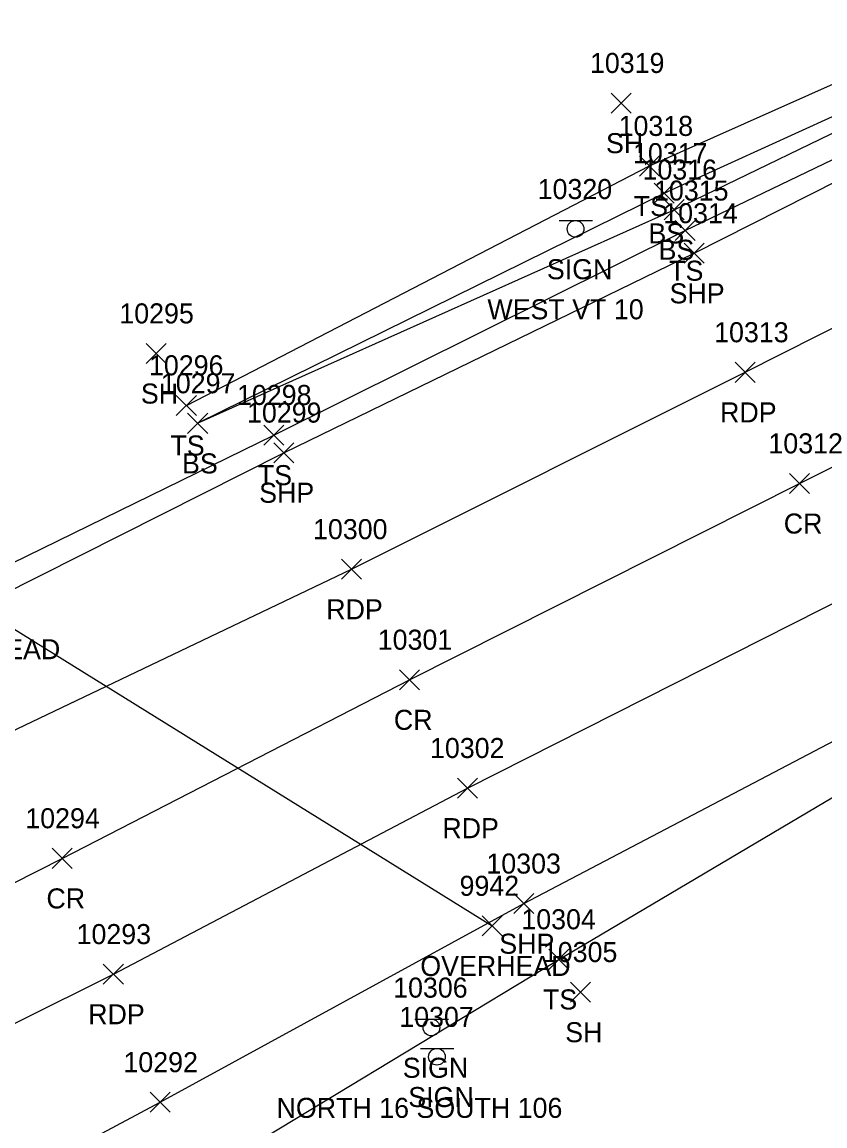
# Model space of a CAD drawing. Extents: x 1611797 to 1633212, y 298978 to 305475.
# Drawn here: x 1631797.1 to 1631877.3, y 304995.4 to 305105.6 of the extents above; entities that cross this region are included whole.
import ezdxf

# ---------------------------------------------------------------- set-up
doc = ezdxf.new("R2010")
doc.units = 0
for name, color, linetype in [('L_A', 7, 'Continuous'), ('L_I', 7, 'Continuous'), ('L_TIC', 7, 'Continuous'), ('LELB', 7, 'Continuous'), ('P_A', 7, 'Continuous'), ('P_I', 7, 'Continuous'), ('P_TIC', 7, 'Continuous'), ('PET', 7, 'Continuous'), ('PRC', 7, 'Continuous'), ('PSP', 7, 'Continuous'), ('S_A', 7, 'Continuous'), ('S_C', 7, 'Continuous'), ('S_I', 7, 'Continuous'), ('SSGN', 7, 'Continuous'), ('U_A', 7, 'Continuous'), ('U_I', 7, 'Continuous'), ('U_TIC', 7, 'Continuous'), ('UCO', 7, 'Continuous')]:
    doc.layers.add(name, color=color, linetype=linetype)

msp = doc.modelspace()

# ---------------------------------------------------------------- linework, layer by layer
at = {"layer": 'L_TIC'}
for points in [[(1631855.91, 305096.52), (1631857.91, 305098.52)], [(1631857.91, 305096.52), (1631855.91, 305098.52)], [(1631858.76, 305090.24), (1631860.76, 305092.24)], [(1631860.76, 305090.24), (1631858.76, 305092.24)], [(1631860.2, 305087.52), (1631862.2, 305089.52)], [(1631862.2, 305087.52), (1631860.2, 305089.52)], [(1631861.21, 305085.88), (1631863.21, 305087.88)], [(1631863.21, 305085.88), (1631861.21, 305087.88)], [(1631862.3, 305083.79), (1631864.3, 305085.79)], [(1631864.3, 305083.79), (1631862.3, 305085.79)], [(1631809.48, 305071.53), (1631811.48, 305073.53)], [(1631811.48, 305071.53), (1631809.48, 305073.53)], [(1631812.5, 305066.35), (1631814.5, 305068.35)], [(1631814.5, 305066.35), (1631812.5, 305068.35)], [(1631813.63, 305064.56), (1631815.63, 305066.56)], [(1631815.63, 305064.56), (1631813.63, 305066.56)], [(1631813.63, 305064.56), (1631815.63, 305066.56)], [(1631815.63, 305064.56), (1631813.63, 305066.56)], [(1631821.23, 305063.39), (1631823.23, 305065.39)], [(1631823.23, 305063.39), (1631821.23, 305065.39)], [(1631849.7, 305011.07), (1631851.7, 305013.07)], [(1631851.7, 305011.07), (1631849.7, 305013.07)], [(1631851.85, 305007.8), (1631853.85, 305009.8)], [(1631853.85, 305007.8), (1631851.85, 305009.8)]]:
    msp.add_lwpolyline(points, dxfattribs=at)
at = {"layer": 'LELB'}
for points in [[(1631813.5, 305067.35), (1631859.76, 305091.24), (1631897.69, 305108.2), (1631899.73, 305104.65), (1631898.88, 305101.89)], [(1631814.63, 305065.56), (1631862.21, 305086.88), (1631898.64, 305104.51), (1631898.18, 305105.36)], [(1631814.63, 305065.56), (1631861.2, 305088.52), (1631898.18, 305105.36)], [(1631737.75, 305080.97), (1631752.89, 305065.4), (1631758.55, 305051.18), (1631777.74, 305046.24), (1631785.26, 305046.31), (1631822.23, 305064.39), (1631863.3, 305084.79), (1631898.88, 305101.89)], [(1631813.04, 304989.3), (1631850.7, 305012.07), (1631886.59, 305033.31), (1631927.2, 305056), (1631951.74, 305069.27), (1631987.35, 305084.79)]]:
    msp.add_lwpolyline(points, dxfattribs=at)
at = {"layer": 'P_TIC'}
for points in [[(1631863.22, 305081.53), (1631865.22, 305083.53)], [(1631865.22, 305081.53), (1631863.22, 305083.53)], [(1631868.31, 305069.65), (1631870.31, 305071.65)], [(1631870.31, 305069.65), (1631868.31, 305071.65)], [(1631822.24, 305061.63), (1631824.24, 305063.63)], [(1631824.24, 305061.63), (1631822.24, 305063.63)], [(1631873.72, 305058.56), (1631875.72, 305060.56)], [(1631875.72, 305058.56), (1631873.72, 305060.56)], [(1631828.98, 305050), (1631830.98, 305052)], [(1631830.98, 305050), (1631828.98, 305052)], [(1631834.79, 305038.97), (1631836.79, 305040.97)], [(1631836.79, 305038.97), (1631834.79, 305040.97)], [(1631840.58, 305028.16), (1631842.58, 305030.16)], [(1631842.58, 305028.16), (1631840.58, 305030.16)], [(1631800.09, 305021.15), (1631802.09, 305023.15)], [(1631802.09, 305021.15), (1631800.09, 305023.15)], [(1631846.21, 305016.63), (1631848.21, 305018.63)], [(1631848.21, 305016.63), (1631846.21, 305018.63)], [(1631805.21, 305009.59), (1631807.21, 305011.59)], [(1631807.21, 305009.59), (1631805.21, 305011.59)], [(1631809.89, 304996.81), (1631811.89, 304998.81)], [(1631811.89, 304996.81), (1631809.89, 304998.81)]]:
    msp.add_lwpolyline(points, dxfattribs=at)
at = {"layer": 'PET'}
for points in [[(1631183.34, 304791.4), (1631232.9, 304801.54), (1631259.87, 304809.61), (1631303.32, 304818.5), (1631347.23, 304832.3), (1631406.32, 304851.58), (1631447.64, 304867.42), (1631474.25, 304878.03), (1631503.98, 304890.8), (1631541.83, 304907.71), (1631577.86, 304925.01), (1631610.67, 304941.1), (1631649.68, 304961.09), (1631665.91, 304969.55), (1631742.05, 305007.18), (1631780.14, 305027.51), (1631792.88, 305033.31), (1631829.98, 305051), (1631869.31, 305070.65), (1631909.86, 305091.12), (1631934.44, 305104.26), (1631965.75, 305123.46), (1631987.63, 305140.55)], [(1631203.79, 304770.25), (1631240.39, 304777.7), (1631272.72, 304785.22), (1631327.79, 304798.8), (1631364.11, 304808.11), (1631417.62, 304827.43), (1631458.87, 304844.05), (1631512.54, 304866.05), (1631551.24, 304883.71), (1631588.3, 304901.31), (1631622.6, 304918.31), (1631660.01, 304936.75), (1631706.66, 304960.79), (1631744.76, 304978.68), (1631787.03, 305001.06), (1631806.21, 305010.59), (1631841.58, 305029.16), (1631879.96, 305048.56), (1631920.69, 305068.82), (1631946.13, 305081.47), (1631980.41, 305098.3)]]:
    msp.add_lwpolyline(points, dxfattribs=at)
at = {"layer": 'PRC'}
msp.add_lwpolyline([(1631200.62, 304781.01), (1631237.62, 304788.44), (1631269.78, 304796.32), (1631289.17, 304801.14), (1631316.43, 304808.32), (1631350.63, 304818.84), (1631382.54, 304828.95), (1631413.53, 304839.65), (1631454.69, 304855.19), (1631506.18, 304877.09), (1631546.86, 304895.1), (1631583.34, 304912.78), (1631616.64, 304929.19), (1631656.09, 304948.53), (1631703.22, 304972.24), (1631736.47, 304989.35), (1631781.29, 305012.13), (1631801.09, 305022.15), (1631835.79, 305039.97), (1631874.72, 305059.56), (1631915.06, 305079.69), (1631940.95, 305092.5), (1631974.43, 305108.96)], dxfattribs=at)
at = {"layer": 'PSP'}
for points in [[(1631660.64, 304978.78), (1631708.39, 305003.93), (1631739.89, 305019.51), (1631781.67, 305041.18), (1631786.68, 305044.23), (1631823.24, 305062.63), (1631864.22, 305082.53), (1631901.7, 305101.51), (1631922.62, 305110.54), (1631929.19, 305113.61), (1631937.65, 305118.42), (1631959.84, 305130.52), (1631984.19, 305145.84), (1632002.78, 305163.05), (1632018.89, 305182.91), (1632031.51, 305200.67)], [(1631214.13, 304760.88), (1631250.98, 304766.05), (1631276.49, 304772.06), (1631292.6, 304776.47), (1631332.75, 304787.13), (1631366.84, 304797.32), (1631383.32, 304801.82), (1631387.74, 304803.79), (1631421.1, 304816.9), (1631462.96, 304835.1), (1631515.58, 304858.84), (1631554.35, 304876.64), (1631591.62, 304893.96), (1631626.33, 304910.11), (1631679.82, 304933.94), (1631714.5, 304949.1), (1631757.18, 304970.65), (1631793.91, 304988.76), (1631810.89, 304997.81), (1631847.21, 305017.63), (1631885.01, 305037.47), (1631925.26, 305059.52), (1631950, 305072.86), (1631984.07, 305090.24)]]:
    msp.add_lwpolyline(points, dxfattribs=at)
at = {"layer": 'SSGN'}
for p, q in [((1631850.71, 305085.79), (1631854.05, 305085.79)), ((1631852.36, 305084.96), (1631852.36, 305084.96)), ((1631836.32, 305006.1), (1631839.66, 305006.1)), ((1631837.97, 305005.27), (1631837.97, 305005.27)), ((1631836.88, 305003.18), (1631840.21, 305003.18)), ((1631838.52, 305002.35), (1631838.52, 305002.35))]:
    msp.add_line(p, q, dxfattribs=at)
for centre in [(1631852.36, 305084.96), (1631837.97, 305005.27), (1631838.52, 305002.35)]:
    msp.add_circle(centre, 0.833, dxfattribs=at)
at = {"layer": 'U_TIC'}
for points in [[(1631843.04, 305014.41), (1631845.04, 305016.41)], [(1631845.04, 305014.41), (1631843.04, 305016.41)]]:
    msp.add_lwpolyline(points, dxfattribs=at)
at = {"layer": 'UCO'}
msp.add_lwpolyline([(1631793.09, 305047.02), (1631844.04, 305015.41)], dxfattribs=at)

# ---------------------------------------------------------------- texts
at = {"layer": 'L_A'}
for s, p in [('SH', (1631855.4, 305092.52)), ('TS', (1631858.17, 305086.24)), ('BS', (1631859.64, 305083.52)), ('BS', (1631860.65, 305081.88)), ('TS', (1631861.71, 305079.79)), ('SH', (1631808.96, 305067.53)), ('TS', (1631811.91, 305062.35)), ('BS', (1631813.07, 305060.56)), ('BS', (1631813.07, 305060.56)), ('TS', (1631820.64, 305059.39)), ('TS', (1631849.11, 305007.07)), ('SH', (1631851.33, 305003.8))]:
    msp.add_text(s, height=2, dxfattribs=at).set_placement(p)
at = {"layer": 'L_I'}
for s, p in [('10319', (1631853.8, 305100.52)), ('10318', (1631856.66, 305094.24)), ('10317', (1631858.1, 305091.52)), ('10316', (1631859.05, 305089.88)), ('10315', (1631860.2, 305087.79)), ('10295', (1631806.81, 305075.53)), ('10296', (1631809.77, 305070.35)), ('10297', (1631810.96, 305068.56)), ('10297', (1631810.96, 305068.56)), ('10298', (1631818.56, 305067.39)), ('10304', (1631846.95, 305015.07)), ('10305', (1631849.1, 305011.8))]:
    msp.add_text(s, height=2, dxfattribs=at).set_placement(p)
at = {"layer": 'P_A'}
for s, p in [('SHP', (1631861.75, 305077.53)), ('RDP', (1631866.79, 305065.65)), ('SHP', (1631820.77, 305057.63)), ('CR', (1631873.15, 305054.56)), ('RDP', (1631827.47, 305046)), ('CR', (1631834.22, 305034.97)), ('RDP', (1631839.06, 305024.16)), ('CR', (1631799.53, 305017.15)), ('SHP', (1631844.75, 305012.63)), ('RDP', (1631803.7, 305005.59))]:
    msp.add_text(s, height=2, dxfattribs=at).set_placement(p)
at = {"layer": 'P_I'}
for s, p in [('10314', (1631861.12, 305085.53)), ('10313', (1631866.2, 305073.65)), ('10299', (1631819.56, 305065.63)), ('10312', (1631871.62, 305062.56)), ('10300', (1631826.15, 305054)), ('10301', (1631832.61, 305042.97)), ('10302', (1631837.83, 305032.16)), ('10294', (1631797.42, 305025.15)), ('10303', (1631843.46, 305020.63)), ('10293', (1631802.54, 305013.59)), ('10292', (1631807.22, 305000.81))]:
    msp.add_text(s, height=2, dxfattribs=at).set_placement(p)
at = {"layer": 'S_A'}
for p in [(1631849.5, 305079.94), (1631835.11, 305000.25), (1631835.66, 304997.33)]:
    msp.add_text('SIGN', height=2, dxfattribs=at).set_placement(p)
at = {"layer": 'S_C'}
for s, p in [('WEST VT 10', (1631843.56, 305075.94)), ('NORTH 16 SOUTH 106', (1631822.51, 304996.25))]:
    msp.add_text(s, height=2, dxfattribs=at).set_placement(p)
at = {"layer": 'S_I'}
for s, p in [('10320', (1631848.58, 305087.94)), ('10306', (1631834.15, 305008.25)), ('10307', (1631834.76, 305005.33))]:
    msp.add_text(s, height=2, dxfattribs=at).set_placement(p)
at = {"layer": 'U_A'}
for p in [(1631785.9, 305042.02), (1631836.86, 305010.41)]:
    msp.add_text('OVERHEAD', height=2, dxfattribs=at).set_placement(p)
at = {"layer": 'U_I'}
msp.add_text('9942', height=2, dxfattribs=at).set_placement((1631840.78, 305018.41))

doc.saveas('drawing.dxf')
